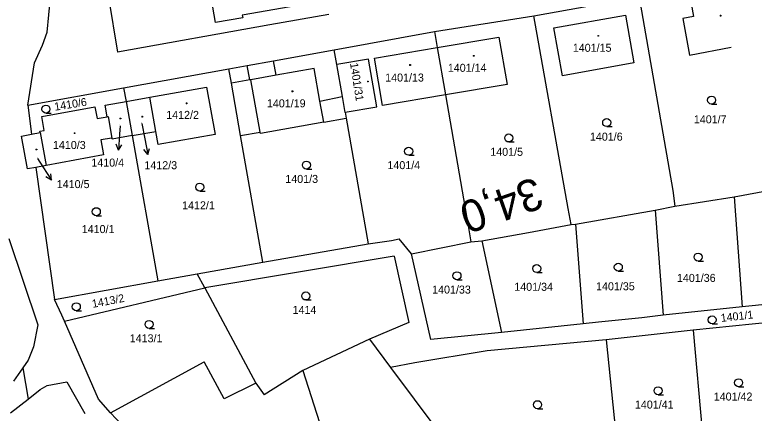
# Model space of a CAD drawing. Extents: x -805730 to -804640, y -1150889 to -1150366.
# Drawn here: x -804924.5 to -804785.9, y -1150513 to -1150438.4 of the extents above; entities that cross this region are included whole.
import ezdxf

# ---------------------------------------------------------------- set-up
doc = ezdxf.new("R2010")
doc.units = 0
for name, color, linetype in [('Default', 7, 'Continuous'), ('kilometráž - vrstava 7', 7, 'Continuous'), ('kn_celek - Cisla parcel pomocna', 7, 'Continuous'), ('kn_celek - Cisla pozemkovych parcel', 7, 'Continuous'), ('kn_celek - Cisla stavebnich parcel', 7, 'Continuous'), ('kn_celek - Hranice parcel', 7, 'Continuous'), ('kn_celek - Vnitrni kresby', 7, 'Continuous'), ('kn_celek - Znacky budov', 7, 'Continuous'), ('kn_celek - Znacky kultur', 7, 'Continuous')]:
    doc.layers.add(name, color=color, linetype=linetype)

# ---------------------------------------------------------------- blocks, each defined once
blk = doc.blocks.new('304')
at = {"layer": 'Default'}
blk.add_line((-0.1, 0), (9.9, 0), dxfattribs=at)
blk.add_circle((-0.1, 7.5), 7.5, dxfattribs=at)
blk = doc.blocks.new('402')
at = {"layer": 'Default'}
for p, q in [((-0.8, 0.8), (0.7, 0.8)), ((-0.8, 0.8), (-0.8, -0.7)), ((0.7, 0.8), (0.7, -0.7)), ((0.7, -0.7), (-0.8, -0.7))]:
    blk.add_line(p, q, dxfattribs=at)
blk = doc.blocks.new('Z61')
at = {"layer": 'Default'}
for p, q in [((0, 0), (30, 0)), ((30, 0), (19.2, 5.3)), ((30, 0), (19.2, -5.3))]:
    blk.add_line(p, q, dxfattribs=at)

msp = doc.modelspace()

# ---------------------------------------------------------------- linework, layer by layer
at = {"layer": 'kn_celek - Cisla parcel pomocna'}
for p, q in [((-804904.74, -1150459.14), (-804904.86, -1150460.75)), ((-804900.72, -1150458.73), (-804900.15, -1150461.62)), ((-804920.27, -1150465.3), (-804919.28, -1150466.82))]:
    msp.add_line(p, q, dxfattribs=at)
at = {"layer": 'kn_celek - Hranice parcel'}
for p, q in [((-804886.88, -1150439.82), (-804888.61, -1150429.96)), ((-804907.58, -1150431.32), (-804905.24, -1150445.34)), ((-804918.43, -1150441.58), (-804917.82, -1150434.88)), ((-804827.24, -1150438.54), (-804807.5, -1150434.98)), ((-804807.5, -1150434.98), (-804801.17, -1150471.28)), ((-804797.73, -1150436.25), (-804797.3, -1150438.65)), ((-804872.92, -1150436.84), (-804881.87, -1150438.42)), ((-804881.78, -1150438.93), (-804886.88, -1150439.82)), ((-804881.87, -1150438.42), (-804881.78, -1150438.93)), ((-804865.63, -1150438.29), (-804876.69, -1150440.25)), ((-804845.86, -1150441.5), (-804827.24, -1150438.54)), ((-804820.75, -1150474.67), (-804827.24, -1150438.54)), ((-804823.45, -1150440.77), (-804810.04, -1150438.41)), ((-804810.04, -1150438.41), (-804808.48, -1150447.38)), ((-804797.3, -1150438.65), (-804799.28, -1150439.02)), ((-804799.28, -1150439.02), (-804798.02, -1150445.89)), ((-804876.69, -1150440.25), (-804905.24, -1150445.34)), ((-804919.29, -1150444.05), (-804918.43, -1150441.58)), ((-804864.65, -1150444.9), (-804845.86, -1150441.5)), ((-804845.86, -1150441.5), (-804845.34, -1150444.49)), ((-804821.86, -1150449.76), (-804823.45, -1150440.77)), ((-804845.34, -1150444.49), (-804833.75, -1150442.56)), ((-804833.75, -1150442.56), (-804832.24, -1150451.43)), ((-804920.8, -1150447.34), (-804919.29, -1150444.05)), ((-804857.11, -1150446.46), (-804845.34, -1150444.49)), ((-804845.34, -1150444.49), (-804843.79, -1150453.37)), ((-804798.02, -1150445.89), (-804790.2, -1150444.44)), ((-804876.02, -1150446.95), (-804864.65, -1150444.9)), ((-804864.17, -1150447.66), (-804864.65, -1150444.9)), ((-804922.09, -1150455.31), (-804920.8, -1150447.34)), ((-804880.94, -1150447.83), (-804876.02, -1150446.95)), ((-804858.18, -1150446.65), (-804864.17, -1150447.66)), ((-804856.64, -1150455.61), (-804858.18, -1150446.65)), ((-804855.61, -1150455.35), (-804857.11, -1150446.46)), ((-804808.48, -1150447.38), (-804821.86, -1150449.76)), ((-804904.12, -1150452.01), (-804884.37, -1150448.45)), ((-804884.37, -1150448.45), (-804880.94, -1150447.83)), ((-804883.89, -1150451.18), (-804884.37, -1150448.45)), ((-804864.2, -1150447.66), (-804863.16, -1150453.66)), ((-804864.17, -1150447.66), (-804864.2, -1150447.66)), ((-804882.18, -1150461), (-804883.89, -1150451.18)), ((-804832.24, -1150451.43), (-804843.79, -1150453.37)), ((-804922.09, -1150455.31), (-804904.12, -1150452.01)), ((-804904.12, -1150452.01), (-804903.66, -1150454.6)), ((-804899.19, -1150453.81), (-804888.56, -1150451.94)), ((-804888.56, -1150451.94), (-804886.98, -1150460.8)), ((-804903.66, -1150454.6), (-804899.19, -1150453.81)), ((-804898.08, -1150460.2), (-804899.19, -1150453.81)), ((-804863.16, -1150453.66), (-804862.64, -1150456.64)), ((-804843.79, -1150453.37), (-804855.61, -1150455.35)), ((-804843.79, -1150453.37), (-804839.53, -1150477.9)), ((-804922.09, -1150455.31), (-804921.41, -1150460.73)), ((-804919.47, -1150457.39), (-804909.48, -1150455.63)), ((-804909.48, -1150455.63), (-804909.09, -1150457.8)), ((-804907.6, -1150455.3), (-804903.66, -1150454.6)), ((-804907.22, -1150457.46), (-804907.6, -1150455.3)), ((-804903.66, -1150454.6), (-804902.52, -1150460.99)), ((-804862.6, -1150456.63), (-804856.64, -1150455.61)), ((-804862.6, -1150456.63), (-804862.64, -1150456.64)), ((-804862.6, -1150456.63), (-804862.4, -1150457.75)), ((-804919.01, -1150460.03), (-804919.47, -1150457.39)), ((-804909.09, -1150457.8), (-804907.22, -1150457.46)), ((-804907.22, -1150457.46), (-804907.04, -1150457.43)), ((-804907.04, -1150457.43), (-804906.3, -1150461.45)), ((-804866.61, -1150458.49), (-804878.48, -1150460.6)), ((-804866.61, -1150458.49), (-804862.4, -1150457.75)), ((-804862.4, -1150457.75), (-804858.29, -1150481.27)), ((-804919.8, -1150460.17), (-804919.01, -1150460.03)), ((-804923.27, -1150461.08), (-804921.41, -1150460.73)), ((-804922.14, -1150467.25), (-804923.27, -1150461.08)), ((-804921.41, -1150460.73), (-804919.76, -1150460.42)), ((-804919.76, -1150460.42), (-804919.8, -1150460.17)), ((-804919.76, -1150460.42), (-804918.66, -1150466.6)), ((-804906.3, -1150461.45), (-804908.39, -1150461.8)), ((-804906.26, -1150461.66), (-804906.3, -1150461.45)), ((-804902.52, -1150460.99), (-804906.26, -1150461.66)), ((-804902.52, -1150460.99), (-804898.08, -1150460.2)), ((-804902.52, -1150460.99), (-804897.67, -1150488.22)), ((-804897.65, -1150462.66), (-804898.08, -1150460.2)), ((-804886.98, -1150460.8), (-804897.65, -1150462.66)), ((-804882.18, -1150461), (-804878.52, -1150460.35)), ((-804878.03, -1150484.71), (-804882.18, -1150461)), ((-804878.48, -1150460.6), (-804878.52, -1150460.35)), ((-804908.39, -1150461.8), (-804907.89, -1150464.6)), ((-804907.89, -1150464.6), (-804918.66, -1150466.6)), ((-804920.54, -1150466.95), (-804922.14, -1150467.25)), ((-804918.66, -1150466.6), (-804920.54, -1150466.95)), ((-804920.54, -1150466.95), (-804917.06, -1150491.7)), ((-804789.66, -1150472.44), (-804782.01, -1150471.04)), ((-804801.17, -1150471.28), (-804800.76, -1150474.19)), ((-804800.76, -1150474.19), (-804789.66, -1150472.44)), ((-804789.66, -1150472.44), (-804788.15, -1150493.09)), ((-804820.2, -1150477.63), (-804820.75, -1150474.67)), ((-804819.39, -1150477.58), (-804804.48, -1150474.95)), ((-804804.48, -1150474.95), (-804800.76, -1150474.19)), ((-804804.48, -1150474.95), (-804802.96, -1150494.62)), ((-804839.53, -1150477.9), (-804839.04, -1150480.91)), ((-804828.21, -1150479.15), (-804820.2, -1150477.63)), ((-804820.2, -1150477.63), (-804819.39, -1150477.58)), ((-804819.39, -1150477.58), (-804817.98, -1150496.25)), ((-804836.95, -1150480.7), (-804828.21, -1150479.15)), ((-804925.63, -1150480.28), (-804920.17, -1150496.45)), ((-804858.29, -1150481.27), (-804853.92, -1150480.66)), ((-804853.92, -1150480.66), (-804852.45, -1150480.37)), ((-804850.16, -1150483.14), (-804852.45, -1150480.37)), ((-804839.04, -1150480.91), (-804836.95, -1150480.7)), ((-804836.95, -1150480.7), (-804833.29, -1150497.92)), ((-804878.03, -1150484.71), (-804858.29, -1150481.27)), ((-804850.16, -1150483.14), (-804839.04, -1150480.91)), ((-804853.37, -1150483.57), (-804888.9, -1150489.55)), ((-804853.37, -1150483.57), (-804850.64, -1150496)), ((-804846.52, -1150499.21), (-804850.16, -1150483.14)), ((-804890.32, -1150486.91), (-804878.03, -1150484.71)), ((-804897.67, -1150488.22), (-804890.32, -1150486.91)), ((-804888.9, -1150489.55), (-804890.32, -1150486.91)), ((-804917.06, -1150491.7), (-804897.67, -1150488.22)), ((-804915.2, -1150495.76), (-804888.9, -1150489.55)), ((-804888.9, -1150489.55), (-804879.35, -1150507.38)), ((-804915.68, -1150494.66), (-804917.06, -1150491.7)), ((-804772.35, -1150491.38), (-804788.15, -1150493.09)), ((-804788.15, -1150493.09), (-804802.96, -1150494.62)), ((-804915.2, -1150495.76), (-804915.68, -1150494.66)), ((-804802.96, -1150494.62), (-804806.95, -1150495.14)), ((-804908.82, -1150510.39), (-804915.2, -1150495.76)), ((-804850.64, -1150496), (-804858.02, -1150499.15)), ((-804815.09, -1150495.98), (-804817.98, -1150496.25)), ((-804806.95, -1150495.14), (-804815.09, -1150495.98)), ((-804781.47, -1150495.86), (-804797.37, -1150497.46)), ((-804920.17, -1150496.45), (-804921.02, -1150500.55)), ((-804817.98, -1150496.25), (-804833.29, -1150497.92)), ((-804797.37, -1150497.46), (-804813.68, -1150499.24)), ((-804797.37, -1150497.46), (-804795.25, -1150521.16)), ((-804833.29, -1150497.92), (-804846.52, -1150499.21)), ((-804858.02, -1150499.15), (-804870.5, -1150505.04)), ((-804858.02, -1150499.15), (-804854.06, -1150504.46)), ((-804813.68, -1150499.24), (-804835.95, -1150501.36)), ((-804813.68, -1150499.24), (-804811.2, -1150522.83)), ((-804921.02, -1150500.55), (-804921.99, -1150503.09)), ((-804835.95, -1150501.36), (-804849.51, -1150503.6)), ((-804921.99, -1150503.09), (-804923.01, -1150504.53)), ((-804906.56, -1150512.95), (-804889, -1150503.37)), ((-804885.24, -1150510.33), (-804889, -1150503.37)), ((-804849.51, -1150503.6), (-804854.06, -1150504.46)), ((-804854.06, -1150504.46), (-804837.36, -1150526.82)), ((-804923.01, -1150504.53), (-804924.76, -1150507)), ((-804923.01, -1150504.53), (-804922.03, -1150510.36)), ((-804870.5, -1150505.04), (-804877.78, -1150509.55)), ((-804870.5, -1150505.04), (-804865.77, -1150519.74)), ((-804918.45, -1150507.81), (-804914.77, -1150507.17)), ((-804914.77, -1150507.17), (-804911.38, -1150513.07)), ((-804922.03, -1150510.36), (-804919.77, -1150508.58)), ((-804919.77, -1150508.58), (-804918.45, -1150507.81)), ((-804879.35, -1150507.38), (-804885.24, -1150510.33)), ((-804879.35, -1150507.38), (-804877.78, -1150509.55)), ((-804925.34, -1150512.97), (-804922.03, -1150510.36)), ((-804906.56, -1150512.95), (-804908.82, -1150510.39)), ((-804902.3, -1150517.47), (-804906.56, -1150512.95))]:
    msp.add_line(p, q, dxfattribs=at)
at = {"layer": 'kn_celek - Vnitrni kresby'}
for p, q in [((-804875.53, -1150449.68), (-804876.02, -1150446.95)), ((-804880.45, -1150450.56), (-804880.94, -1150447.83)), ((-804868.4, -1150448.41), (-804875.53, -1150449.68)), ((-804867.32, -1150454.51), (-804868.4, -1150448.41)), ((-804875.53, -1150449.68), (-804880.26, -1150450.53)), ((-804880.45, -1150450.56), (-804883.89, -1150451.18)), ((-804880.26, -1150450.53), (-804880.45, -1150450.56)), ((-804878.52, -1150460.35), (-804880.26, -1150450.53)), ((-804867.32, -1150454.51), (-804863.16, -1150453.66)), ((-804866.61, -1150458.49), (-804867.32, -1150454.51))]:
    msp.add_line(p, q, dxfattribs=at)

# ---------------------------------------------------------------- block references
at = {"layer": 'kn_celek - Cisla parcel pomocna'}
for p, xscale, yscale, rotation in [((-804904.86, -1150460.75), 0.1, 0.10000000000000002, -94.10319), ((-804900.15, -1150461.62), 0.09999999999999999, 0.10000000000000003, -78.84143999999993), ((-804919.28, -1150466.82), 0.1, 0.09999999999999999, -56.871449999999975)]:
    msp.add_blockref('Z61', p, dxfattribs=dict(at, xscale=xscale, yscale=yscale, rotation=rotation))
at = {"layer": 'kn_celek - Znacky budov', "xscale": 0.1, "yscale": 0.10000000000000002}
for p in [(-804792.22, -1150438.53), (-804815.16, -1150442.28), (-804838.49, -1150446.03), (-804850.42, -1150447.77), (-804858.34, -1150450.86), (-804872.48, -1150452.69), (-804892.31, -1150454.94), (-804904.72, -1150457.79), (-804900.63, -1150457.44), (-804913.31, -1150460.53), (-804920.47, -1150463.61)]:
    msp.add_blockref('402', p, dxfattribs=at)
at = {"layer": 'kn_celek - Znacky kultur', "xscale": 0.1, "yscale": 0.10000000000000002}
for p in [(-804793.9, -1150455.1), (-804918.66, -1150456.78), (-804813.55, -1150459.29), (-804831.92, -1150462.19), (-804850.67, -1150464.68), (-804869.84, -1150467.26), (-804889.84, -1150471.4), (-804909.22, -1150476), (-804796.41, -1150484.5), (-804811.37, -1150486.4), (-804826.66, -1150486.66), (-804841.61, -1150488), (-804869.95, -1150491.8), (-804912.97, -1150493.81), (-804899.33, -1150497.13), (-804793.78, -1150496.27), (-804788.82, -1150508.05), (-804803.92, -1150509.55), (-804826.51, -1150512.17)]:
    msp.add_blockref('304', p, dxfattribs=at)

# ---------------------------------------------------------------- texts
at = {"layer": 'kilometráž - vrstava 7'}
msp.add_text('34,0', height=6, rotation=199.3195, dxfattribs=at).set_placement((-804826.89, -1150468.65))
at = {"layer": 'kn_celek - Cisla parcel pomocna'}
for s, p in [('1410/4', (-804910.16, -1150466.8)), ('1412/3', (-804900.22, -1150467.29)), ('1410/5', (-804916.64, -1150470.83))]:
    msp.add_text(s, height=1.5, dxfattribs=at).set_placement(p)
at = {"layer": 'kn_celek - Cisla pozemkovych parcel'}
for s, rotation, p in [('1410/6', 9, (-804916.98, -1150456.33)), ('1413/2', 10.8, (-804909.9, -1150493.28)), ('1401/1', 6.3, (-804792.1, -1150495.92))]:
    msp.add_text(s, height=1.5, rotation=rotation, dxfattribs=at).set_placement(p)
for s, p in [('1401/7', (-804797.22, -1150458.69)), ('1401/6', (-804816.7, -1150461.94)), ('1401/5', (-804835.38, -1150464.78)), ('1401/4', (-804854.66, -1150467.28)), ('1401/3', (-804873.8, -1150469.86)), ('1412/1', (-804893.15, -1150474.81)), ('1410/1', (-804911.96, -1150479.26)), ('1401/36', (-804800.39, -1150488.41)), ('1401/33', (-804846.28, -1150490.6)), ('1401/34', (-804830.88, -1150490.08)), ('1401/35', (-804815.55, -1150489.98)), ('1414', (-804872.44, -1150494.4)), ('1413/1', (-804902.97, -1150499.73)), ('1401/42', (-804793.49, -1150510.65)), ('1401/41', (-804808.27, -1150512.15))]:
    msp.add_text(s, height=1.5, dxfattribs=at).set_placement(p)
at = {"layer": 'kn_celek - Cisla stavebnich parcel'}
for s, p in [('1401/15', (-804819.91, -1150445.28)), ('1401/14', (-804843.34, -1150449.03)), ('1401/13', (-804855.08, -1150450.86)), ('1401/19', (-804877.25, -1150455.69)), ('1412/2', (-804896.13, -1150457.86)), ('1410/3', (-804917.36, -1150463.5))]:
    msp.add_text(s, height=1.5, dxfattribs=at).set_placement(p)
for s, height, rotation, p in [('1401/31', 1.5, 279, (-804861.68, -1150447.45)), ('1412/3', 0.1, 279, (-804900.81, -1150458.48)), ('1410/4', 0.1, 279, (-804904.83, -1150458.89)), ('1410/5', 0.1, 280.8, (-804920.37, -1150465.06))]:
    msp.add_text(s, height=height, rotation=rotation, dxfattribs=at).set_placement(p)

doc.saveas('drawing.dxf')
